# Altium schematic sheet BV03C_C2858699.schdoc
size 127 x 101 mm
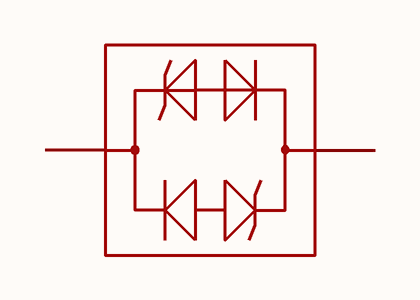
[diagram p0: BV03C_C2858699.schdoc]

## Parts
D?  bv03c_c2858699  [SOD-323_L1.8-W1.3-LS2.5-BI]  (value not drawn)

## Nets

Not connected (* = marked no-connect by the designer): D? 1 2

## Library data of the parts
D? = bv03c_c2858699: 极性:双向;反向截止电压(Vrwm):3.3V;钳位电压:12V;峰值脉冲电流(Ipp):22A;峰值脉冲功率(Ppp):260W@8/20us;击穿电压:6V;; Manufacturer: TECH PUBLIC(台舟); ManufacturerPart: BV03C; AddInBom: yes; ModelId: f9eb3c564310447fa7e5a2d35bef3787; ModelTransform: 98.425,51.181,0,0,0,0,0,0,0; Polarity: 双向; Reverse Stand-Off Voltage (Vrwm): 3.3V; Clamping Voltage: 12V; Peak Pulse Current (Ipp): 22A; Voltage - Breakdown: 6V; Reverse Leakage Current (Ir): 200nA; Number of Channels: 单路; level of protection: IEC 61000-4-2；IEC 61000-4-4; Type: ESD; Junction Capacitance: 1pF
